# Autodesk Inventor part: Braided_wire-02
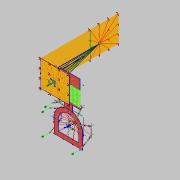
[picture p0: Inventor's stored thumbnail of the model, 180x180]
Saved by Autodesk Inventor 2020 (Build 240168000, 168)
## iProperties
Created: 2016-07
Part Number: Braided_wire-02
Material: Generic
Document SubType Name: Modeling
Designer: kyeongyeon
Density: 1 g/cm^3
Appearance: Default
Sheet Metal Rule: Default
Author: kyeongyeon
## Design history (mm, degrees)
sketch "Sketch1" dims "d18" = 10
  geometry: L1 (0, 7.5)-(-33.5, 7.5); L2 (-33.5, 7.5)-(-33.5, -10.5); L3 (-33.5, -10.5)-(6.5, -10.5); L4 (6.5, -10.5)-(6.5, -3.742); L5 (6.5, -40.5)-(-33.5, -40.5); L6 (-33.5, -40.5)-(-33.5, -43.5); L7 (-33.5, -43.5)-(6.5, -43.5); L8 (6.5, -43.5)-(6.5, -40.5); L9 (16.06, -81.15)-(16.06, -108.65); L10 (16.06, -108.65)-(-38.94, -108.65); L11 (-38.94, -108.65)-(-38.94, -81.15); L12 (8.06, -100.65)-(8.06, -81.15); L13 (-30.94, -81.15)-(-30.94, -100.65); L14 (-30.94, -100.65)-(8.06, -100.65); L15 (-3.3, -43.5)-(-3.3, -54.882); L16 (-19.58, -43.5)-(-19.58, -54.882); L17 (-3.3, -47.475)-(-19.58, -47.475); L18 (6.5, -10.5)-(6.5, -40.5); L19 (4.395, -10.5)-(4.395, -40.5); L20 (2.289, -10.5)-(2.289, -40.5); L21 (0.184, -10.5)-(0.184, -40.5); L22 (-1.921, -10.5)-(-1.921, -40.5); L23 (-4.026, -10.5)-(-4.026, -40.5); L24 (-6.132, -10.5)-(-6.132, -40.5); L25 (-8.237, -10.5)-(-8.237, -40.5); L26 (-10.342, -10.5)-(-10.342, -40.5); L27 (-12.447, -10.5)-(-12.447, -40.5); L28 (-14.553, -10.5)-(-14.553, -40.5); L29 (-16.658, -10.5)-(-16.658, -40.5); L30 (-18.763, -10.5)-(-18.763, -40.5); L31 (-20.868, -10.5)-(-20.868, -40.5); L32 (-22.974, -10.5)-(-22.974, -40.5); L33 (-25.079, -10.5)-(-25.079, -40.5); L34 (-27.184, -10.5)-(-27.184, -40.5); L35 (-29.289, -10.5)-(-29.289, -40.5); L36 (-31.395, -10.5)-(-31.395, -40.5); L37 (-33.5, -10.5)-(-33.5, -40.5); L38 (-11.44, -53.65)-(-11.44, -108.65); L39 (16.06, -108.65)-(8.06, -100.65); L40 (8.06, -100.65)-(-30.885, -61.705); L41 (18.08, -82.166)-(-40.96, -82.166); L42 (15.96, -81.15)-(15.96, -108.55); L43 (15.96, -108.55)-(-38.84, -108.55); L44 (-38.84, -108.55)-(-38.84, -81.15); L45 (-11.44, -83.93)-(-40.44, -83.93); L46 (-40.44, -75.93)-(-40.44, -91.93); L47 (17.56, -75.93)-(17.56, -91.93); L48 (-22.403, -52.15)-(-0.423, -52.15); C1 r 7.4 at (0, 0); A1 r 7.5 centre (0, 0) between (0, 7.5) and (6.5, -3.742); A2 r 19.5 centre (-11.44, -81.15) between (8.06, -81.15) and (-30.94, -81.15); A3 r 27.5 centre (-11.44, -81.15) between (16.06, -81.15) and (-3.3, -54.882); A4 r 27.5 centre (-11.44, -81.15) between (-19.58, -54.882) and (-38.94, -81.15); A5 r 27.5 centre (-11.44, -81.15) between (-3.3, -54.882) and (-19.58, -54.882); A6 r 27.4 centre (-11.44, -81.15) between (15.96, -81.15) and (-38.84, -81.15); 12 further points
  constraints: 96 end point, 14 point on circle, 9 perpendicular, 7 centre point, 7 midpoint, 6 horizontal, 6 point on line, 5 parallel, 4 coincident, 4 vertical alignment, 3 collinear, 3 tangent, 3 vertical, 2 symmetric about line, 1 horizontal alignment, 61 other
  dimensions: "d0" = 15 diameter of A1; "d1" = 40 distance of L2.end L3.end; "d2" = 18 distance of L1.end L2.end; "d3" = 33.5 distance from line of L2 A1.centre; "d4" = 3 distance of L5.end L6.end; "d8" = 8 distance between parallel lines of L9 L12; "d9" = 9.8 distance between parallel lines of L8 L15; "d10" = 13.92 distance between parallel lines of L6 L16; "d11" = 65.15 distance between parallel lines of L10 L7; "Wire_length" = 30 distance between parallel lines of L5 L3; "d15" = 2.10526 distance of L3.end L19.start; "d21" = 55 distance of L38.start L38.end; "d29" = 24.72027 distance from line of L10 L45.start; "d31" = 55 distance between parallel lines of L11 L9; "d32" = 27.5 distance from line of L10 A2.centre; "d33" = 27.5 radius of A3; "d34" = 19.5 radius of A2; "d35" = 39 distance of L13.end L12.start; "d36" = 25.122 distance from line of L10 point (-11.44, -83.528); "d40" = 26.4841 distance from line of L10 L41.end; "d41" = 2.02 distance from line of L11 L41.end; "d42" = 2.02 distance from line of L9 L41.start (= d41); "d43" = 2.019 distance of L38.start point (-11.44, -51.631); "d45" = 4.318 horizontal distance of point (4.318, 3.29) point (0, 0); "d46" = 3.29 vertical distance of point (0, 0) point (4.318, 3.29); "d82" = 7.9 radial gap between concentric circles of A2 A6; "d85" = 14.8 diameter of C1; "d105" = 10.975 horizontal distance of C1.centre point (10.975, 3.158); "d106" = 3.158 vertical distance of C1.centre point (10.975, 3.158); "d108" = 29 distance of L45.end L45.start (computed from d31); "d109" = 16 distance of L46.start L46.end; "d110" = 16 distance of L47.start L47.end (derived); "d120" = 21.98 distance of L48.start L48.end; "d121" = 29 distance from line of L48 A5.centre
patch "Boundary Patch2"
patch "Boundary Patch3"
patch "Boundary Patch4"
patch "Boundary Patch13"
sketch "CG_Cooler" dims "d47" = 44.674
sketch "CG_Coldbox_n_FilterModule" dims "d30" = 13.39984
patch "Boundary Patch8"
sketch "CG_ColdboxBase" dims "d37" = 1.243
sketch "Center_of_supports" dims "d44" = 3.23554, "d86" = 6.8
split "Split1"
node "3D Sketch6" dims "d84" = 52.3
split "Split3"
node "3D Sketch7" dims "d97" = 25.75
workplane "Work Plane6"
sketch "Sketch11"
  geometry: L1 (-16, -30)-(39, -30); L2 (39, -30)-(39, 20); L3 (39, 20)-(-16, 20); L4 (-16, 20)-(-16, -30); 4 further points
  constraints: 8 end point, 2 midpoint, 2 parallel, 1 horizontal, 1 horizontal alignment, 1 perpendicular, 1 vertical alignment
  dimensions: "d98" = 50 distance of L1.end L2.end; "d99" = 30 distance from line of L1 point (0, 0); "d100" = 16 distance from line of L4 point (0, 0); "d101" = 55 distance of L1.start L1.end
patch "Boundary Patch14" sketch "Sketch11"
sketch "3D Sketch8" dims "d102" = 150, "d103" = 50
patch "Boundary Patch15" sketch "3D Sketch8" dims "d104" = 0
sketch "Sketch15"
  geometry: L1 (0, 150)-(-50, 150) reference; L2 (-50, 0)-(-50, 150) reference; L3 (0, 150)-(-50, 150); L4 (-50, 150)-(-50, 95.25); L5 (-50, 95.25)-(0, 95.25); L6 (0, 95.25)-(0, 150); 1 further point
  constraints: 8 end point, 2 parallel, 1 horizontal, 1 perpendicular, 1 point on line
  dimensions: "d130" = 54.75 distance between parallel lines of L1 L5
split "Split4" sketch "Sketch15"
sketch "3D Sketch9" dims "d107" = 82.873
workplane "Work Plane7"
workplane "Work Plane8"
sketch "Sketch13"
  geometry: L1 (0, 15.462)-(16, 15.462); L2 (16, 15.462)-(28.69, -6.518); L3 (0, 15.462)-(-12.69, -6.518); 1 further point
  constraints: 6 end point, 2 coincident, 1 horizontal
  dimensions: "d149" = 120 deg angle of L2 L1; "d150" = 120 deg angle of L3 L1; "d151" = 21.98 distance from line of L2.end L1 (derived); "d152" = 21.98 distance from line of L3.end L1 (derived)
workplane "Work Plane9"
sketch "Sketch14"
  geometry: L1 (0, 0)-(21.98, 0) reference; L2 (21.961, 15.462)-(34.651, -6.518); L3 (-0.036, 15.462)-(-12.726, -6.518); L4 (21.961, 15.462)-(-0.036, 15.462); L5 (38.463, 0)-(-16.537, 0) reference; 6 further points
  constraints: 6 end point, 3 midpoint, 2 coincident, 1 horizontal, 1 horizontal alignment, 1 vertical alignment
  dimensions: "d153" = 21.99669 distance of L2.start L3.start; "d154" = 120 deg angle of L2 L4; "d155" = 120 deg angle of L3 L4; "d156" = 21.98 distance from line of L2.end L4 (derived); "d157" = 6.518 distance from line of L5 L3.end (derived)
sketch "Sketch16"
  geometry: L1 (50, 95.25)-(0, 95.25) reference; 3 further points
  constraints: 1 midpoint, 1 vertical alignment
body "Solid2"
sketch "Sketch12"
  geometry: L1 (0, 0)-(16, 0) reference; L2 (0, 15.462)-(-12.69, -6.518); L3 (16, 15.462)-(28.69, -6.518); L4 (0, 15.462)-(16, 15.462); L5 (5.22, 0)-(-22.28, 0) reference; 6 further points
  constraints: 6 end point, 2 coincident, 2 midpoint, 2 vertical alignment, 1 horizontal, 1 horizontal alignment
  dimensions: "d143" = 120 deg angle of L4 L2; "d144" = 21.98 distance from line of L2.end L4; "d145" = 6.518 distance from line of L5 L2.end; "d146" = 120 deg angle of L3 L4; "d148" = 16 distance of L2.start L3.start
body "Srf2"
body "Srf3"
body "Srf4"
body "Srf8"
body "Srf15"
body "Srf16"
body "Srf17"
other parameters: "d5" = 55, "Thickness" = 3 (derived), "KFactor" = 4.4, "BendRadius" = 3 (= Thickness), "BendReliefWidth" = 3 (= Thickness), "BendReliefDepth" = 1.5 (= 0.5 x Thickness), "CornerReliefSize" = 12 (= 4 x Thickness), "SeamGap" = 0.01, "MinimumRemnant" = 6 (= 2 x Thickness), "TransitionRadius" = 3 (= BendRadius), "JacobiRadiusSize" = 3 (= Thickness), "GapSize" = 3 (= Thickness), "d22" = 3 (= BendRadius), "d111" = 90 deg, "d119" = 90 deg, "d122" = 90 deg
